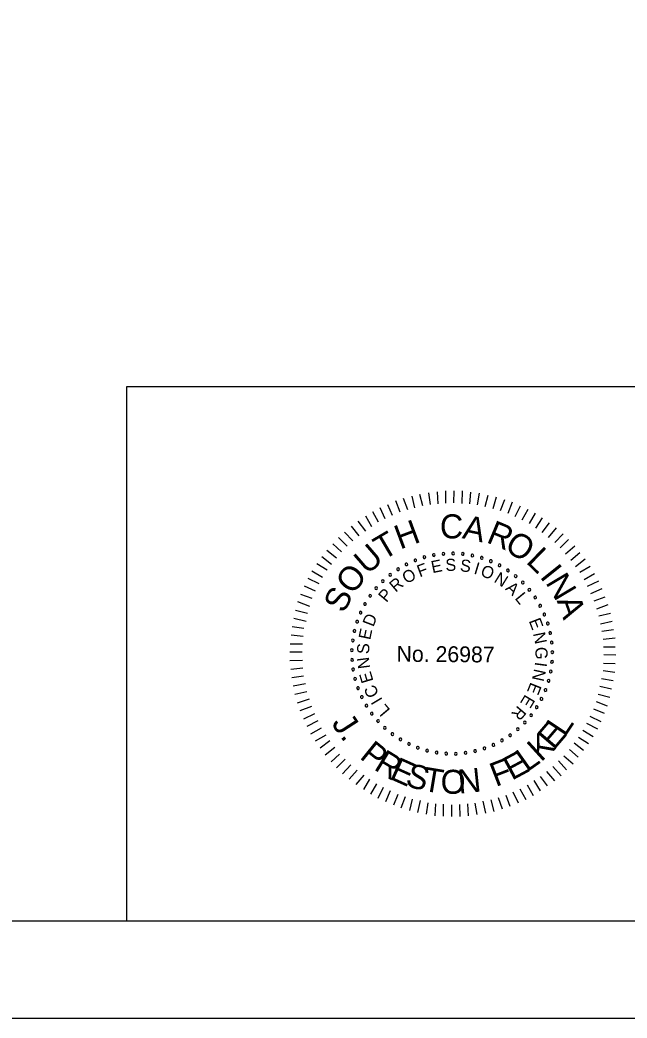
# Model space of a CAD drawing. Extents: x 96 to 240, y 601 to 689.
# Drawn here: x 184.17 to 196.67, y 601 to 621.55 of the extents above; entities that cross this region are included whole.
import ezdxf

# ---------------------------------------------------------------- set-up
doc = ezdxf.new("R2010")
doc.units = 0
for name, color, linetype in [('BR_BORDER LINES', 7, 'Continuous'), ('BR_TEXT', 7, 'Continuous'), ('Level 31', 7, 'Continuous')]:
    doc.layers.add(name, color=color, linetype=linetype)

msp = doc.modelspace()

# ---------------------------------------------------------------- linework, layer by layer
at = {"layer": 'BR_BORDER LINES'}
for p, q in [((186.375, 614.004), (207.836, 614.004)), ((186.375, 603.004), (186.375, 614.004)), ((103.173, 603.003), (237.837, 603.003))]:
    msp.add_line(p, q, dxfattribs=at)
at = {"layer": 'BR_TEXT'}
for p, q in [((192.299, 611.507), (192.246, 611.751)), ((192.464, 611.546), (192.407, 611.784)), ((192.622, 611.576), (192.586, 611.82)), ((192.78, 611.592), (192.765, 611.836)), ((192.938, 611.601), (192.94, 611.858)), ((193.106, 611.61), (193.108, 611.857)), ((193.274, 611.598), (193.283, 611.856)), ((193.435, 611.587), (193.455, 611.83)), ((193.59, 611.568), (193.633, 611.811)), ((193.751, 611.536), (193.808, 611.772)), ((193.915, 611.493), (193.979, 611.736)), ((191.841, 611.349), (191.747, 611.573)), ((191.996, 611.416), (191.912, 611.651)), ((192.154, 611.467), (192.067, 611.697)), ((194.063, 611.451), (194.15, 611.68)), ((194.22, 611.398), (194.308, 611.631)), ((194.364, 611.328), (194.475, 611.55)), ((191.413, 611.116), (191.292, 611.333)), ((191.555, 611.211), (191.433, 611.428)), ((191.693, 611.282), (191.588, 611.506)), ((194.507, 611.258), (194.633, 611.481)), ((194.658, 611.185), (194.787, 611.4)), ((191.154, 610.929), (190.995, 611.13)), ((191.289, 611.031), (191.133, 611.235)), ((194.791, 611.088), (194.927, 611.303)), ((194.924, 611.001), (195.07, 611.202)), ((191.023, 610.831), (190.856, 611.01)), ((195.054, 610.897), (195.216, 611.095)), ((195.18, 610.796), (195.353, 610.973)), ((190.788, 610.599), (190.614, 610.769)), ((190.905, 610.722), (190.728, 610.898)), ((195.292, 610.686), (195.465, 610.859)), ((195.404, 610.561), (195.595, 610.728)), ((190.687, 610.473), (190.489, 610.629)), ((195.513, 610.433), (195.7, 610.586)), ((190.496, 610.224), (190.281, 610.356)), ((190.583, 610.34), (190.385, 610.5)), ((195.608, 610.298), (195.805, 610.455)), ((195.696, 610.181), (195.907, 610.31)), ((190.399, 610.077), (190.184, 610.206)), ((195.784, 610.033), (195.998, 610.158)), ((190.259, 609.793), (190.03, 609.895)), ((190.329, 609.94), (190.103, 610.052)), ((195.855, 609.895), (196.086, 610.003)), ((190.189, 609.639), (189.957, 609.727)), ((195.926, 609.747), (196.154, 609.844)), ((190.14, 609.479), (189.894, 609.57)), ((195.994, 609.592), (196.221, 609.675)), ((196.047, 609.43), (196.278, 609.517)), ((190.091, 609.335), (189.847, 609.395)), ((196.087, 609.285), (196.328, 609.342)), ((190.062, 609.167), (189.812, 609.231)), ((196.12, 609.117), (196.361, 609.177)), ((190.001, 608.858), (189.754, 608.888)), ((190.019, 609.023), (189.776, 609.056)), ((196.153, 608.972), (196.39, 609.001)), ((189.989, 608.701), (189.732, 608.703)), ((196.179, 608.807), (196.423, 608.833)), ((189.981, 608.536), (189.73, 608.538)), ((196.185, 608.649), (196.425, 608.647)), ((196.194, 608.485), (196.438, 608.483)), ((189.986, 608.364), (189.729, 608.359)), ((196.182, 608.313), (196.422, 608.304)), ((189.996, 608.21), (189.748, 608.181)), ((190.011, 608.045), (189.767, 608.009)), ((196.174, 608.159), (196.418, 608.126)), ((190.051, 607.887), (189.8, 607.834)), ((196.11, 607.837), (196.349, 607.78)), ((196.145, 607.994), (196.382, 607.954)), ((190.077, 607.718), (189.833, 607.662)), ((196.074, 607.669), (196.314, 607.608)), ((190.124, 607.57), (189.876, 607.486)), ((196.031, 607.521), (196.261, 607.434)), ((190.171, 607.415), (189.937, 607.331)), ((190.238, 607.267), (190.007, 607.159)), ((195.905, 607.22), (196.131, 607.109)), ((195.975, 607.367), (196.201, 607.28)), ((190.306, 607.122), (190.078, 607.004)), ((195.832, 607.077), (196.061, 606.955)), ((190.373, 606.974), (190.156, 606.849)), ((190.468, 606.826), (190.251, 606.701)), ((195.759, 606.93), (195.971, 606.801)), ((190.553, 606.708), (190.353, 606.562)), ((195.578, 606.667), (195.773, 606.518)), ((195.668, 606.783), (195.877, 606.654)), ((190.655, 606.574), (190.454, 606.417)), ((190.753, 606.439), (190.577, 606.276)), ((195.37, 606.401), (195.557, 606.234)), ((195.481, 606.534), (195.665, 606.374)), ((190.869, 606.335), (190.689, 606.155)), ((190.985, 606.214), (190.815, 606.03)), ((195.256, 606.299), (195.426, 606.115)), ((191.114, 606.11), (190.952, 605.922)), ((191.248, 606.006), (191.088, 605.815)), ((195.014, 606.078), (195.173, 605.888)), ((195.142, 606.18), (195.312, 605.993)), ((191.37, 605.919), (191.245, 605.711)), ((191.51, 605.829), (191.385, 605.613)), ((194.613, 605.803), (194.739, 605.586)), ((194.748, 605.891), (194.88, 605.681)), ((194.883, 605.976), (195.025, 605.782)), ((191.647, 605.749), (191.539, 605.526)), ((191.794, 605.679), (191.696, 605.456)), ((191.948, 605.609), (191.86, 605.383)), ((194.172, 605.59), (194.256, 605.363)), ((194.317, 605.658), (194.425, 605.434)), ((194.462, 605.725), (194.583, 605.501)), ((192.105, 605.559), (192.014, 605.327)), ((192.249, 605.51), (192.192, 605.274)), ((192.414, 605.481), (192.353, 605.235)), ((192.571, 605.435), (192.532, 605.202)), ((192.729, 605.417), (192.71, 605.17)), ((192.887, 605.405), (192.885, 605.158)), ((193.055, 605.394), (193.053, 605.15)), ((193.223, 605.403), (193.228, 605.155)), ((193.384, 605.412), (193.4, 605.164)), ((193.539, 605.427), (193.578, 605.194)), ((193.701, 605.471), (193.754, 605.223)), ((193.866, 605.497), (193.926, 605.259)), ((194.014, 605.544), (194.098, 605.309))]:
    msp.add_line(p, q, dxfattribs=at)
for centre, start, end in [((192.498, 610.49), 16.1422, 196.1422), ((192.692, 610.536), 10.6038, 190.6038), ((192.692, 610.536), 190.6038, 10.6038), ((192.89, 610.563), 5.0653, 185.0653), ((192.89, 610.563), 185.0653, 5.0653), ((193.089, 610.57), 359.5268, 179.5268), ((193.089, 610.57), 179.5268, 359.5268), ((193.288, 610.558), 353.9884, 173.9884), ((193.288, 610.558), 173.9884, 353.9884), ((193.485, 610.528), 348.4499, 168.4499), ((193.485, 610.528), 168.4499, 348.4499), ((193.678, 610.478), 342.9114, 162.9114), ((192.128, 610.344), 27.2191, 207.2191), ((192.128, 610.344), 207.2191, 27.2191), ((192.31, 610.426), 21.6807, 201.6807), ((192.31, 610.426), 201.6807, 21.6807), ((192.498, 610.49), 196.1422, 16.1422), ((193.678, 610.478), 162.9114, 342.9114), ((193.865, 610.41), 157.373, 337.373), ((193.865, 610.41), 337.373, 157.373), ((194.045, 610.324), 151.8345, 331.8345), ((194.045, 610.324), 331.8345, 151.8345), ((191.793, 610.129), 38.2961, 218.2961), ((191.793, 610.129), 218.2961, 38.2961), ((191.955, 610.244), 32.7576, 212.7576), ((191.955, 610.244), 212.7576, 32.7576), ((194.216, 610.221), 146.2961, 326.2961), ((194.216, 610.221), 326.2961, 146.2961), ((194.376, 610.102), 140.7576, 320.7576), ((194.376, 610.102), 320.7576, 140.7576), ((191.642, 609.998), 43.8345, 223.8345), ((191.642, 609.998), 223.8345, 43.8345), ((194.524, 609.969), 135.2191, 315.2191), ((194.524, 609.969), 315.2191, 135.2191), ((191.382, 609.697), 54.9114, 234.9114), ((191.382, 609.697), 234.9114, 54.9114), ((191.505, 609.854), 49.373, 229.373), ((191.505, 609.854), 229.373, 49.373), ((194.658, 609.821), 129.6807, 309.6807), ((194.658, 609.821), 309.6807, 129.6807), ((194.777, 609.662), 124.1422, 304.1422), ((194.777, 609.662), 304.1422, 124.1422), ((191.275, 609.528), 60.4499, 240.4499), ((191.275, 609.528), 240.4499, 60.4499), ((194.881, 609.491), 118.6038, 298.6038), ((194.881, 609.491), 298.6038, 118.6038), ((191.185, 609.351), 65.9884, 245.9884), ((191.185, 609.351), 245.9884, 65.9884), ((194.967, 609.312), 113.0653, 293.0653), ((194.967, 609.312), 293.0653, 113.0653), ((191.113, 609.165), 71.5268, 251.5268), ((191.113, 609.165), 251.5268, 71.5268), ((195.036, 609.125), 107.5268, 287.5268), ((195.036, 609.125), 287.5268, 107.5268), ((191.058, 608.973), 77.0653, 257.0653), ((191.058, 608.973), 257.0653, 77.0653), ((195.087, 608.932), 101.9884, 281.9884), ((195.087, 608.932), 281.9884, 101.9884), ((191.023, 608.777), 82.6038, 262.6038), ((191.023, 608.777), 262.6038, 82.6038), ((195.118, 608.735), 96.4499, 276.4499), ((195.118, 608.735), 276.4499, 96.4499), ((191.006, 608.578), 88.1422, 268.1422), ((191.006, 608.578), 268.1422, 88.1422), ((195.131, 608.536), 90.9114, 270.9114), ((195.131, 608.536), 270.9114, 90.9114), ((191.009, 608.379), 93.6807, 273.6807), ((191.009, 608.379), 273.6807, 93.6807), ((195.124, 608.337), 85.373, 265.373), ((195.124, 608.337), 265.373, 85.373), ((191.031, 608.181), 99.2191, 279.2191), ((191.031, 608.181), 279.2191, 99.2191), ((195.098, 608.139), 79.8345, 259.8345), ((195.098, 608.139), 259.8345, 79.8345), ((191.072, 607.986), 104.7576, 284.7576), ((191.072, 607.986), 284.7576, 104.7576), ((195.053, 607.945), 74.2961, 254.2961), ((195.053, 607.945), 254.2961, 74.2961), ((191.132, 607.796), 110.2961, 290.2961), ((191.132, 607.796), 290.2961, 110.2961), ((191.209, 607.612), 115.8345, 295.8345), ((191.209, 607.612), 295.8345, 115.8345), ((194.989, 607.756), 68.7576, 248.7576), ((194.989, 607.756), 248.7576, 68.7576), ((191.305, 607.437), 121.373, 301.373), ((191.305, 607.437), 301.373, 121.373), ((194.809, 607.401), 57.6807, 237.6807), ((194.809, 607.401), 237.6807, 57.6807), ((194.908, 607.574), 63.2191, 243.2191), ((194.908, 607.574), 243.2191, 63.2191), ((191.416, 607.272), 126.9114, 306.9114), ((191.416, 607.272), 306.9114, 126.9114), ((194.694, 607.238), 52.1422, 232.1422), ((194.694, 607.238), 232.1422, 52.1422), ((191.543, 607.118), 132.4499, 312.4499), ((191.543, 607.118), 312.4499, 132.4499), ((194.564, 607.087), 46.6038, 226.6038), ((194.564, 607.087), 226.6038, 46.6038), ((191.684, 606.977), 137.9884, 317.9884), ((191.684, 606.977), 317.9884, 137.9884), ((191.838, 606.851), 143.5268, 323.5268), ((191.838, 606.851), 323.5268, 143.5268), ((194.263, 606.826), 35.5268, 215.5268), ((194.263, 606.826), 215.5268, 35.5268), ((194.42, 606.949), 41.0653, 221.0653), ((194.42, 606.949), 221.0653, 41.0653), ((192.004, 606.74), 149.0653, 329.0653), ((192.004, 606.74), 329.0653, 149.0653), ((192.18, 606.646), 154.6038, 334.6038), ((192.18, 606.646), 334.6038, 154.6038), ((193.918, 606.628), 24.4499, 204.4499), ((193.918, 606.628), 204.4499, 24.4499), ((194.095, 606.719), 29.9884, 209.9884), ((194.095, 606.719), 209.9884, 29.9884), ((192.363, 606.569), 160.1422, 340.1422), ((192.363, 606.569), 340.1422, 160.1422), ((192.554, 606.51), 165.6807, 345.6807), ((192.554, 606.51), 345.6807, 165.6807), ((192.749, 606.469), 351.2191, 171.2191), ((192.749, 606.469), 171.2191, 351.2191), ((192.947, 606.448), 356.7576, 176.7576), ((192.947, 606.448), 176.7576, 356.7576), ((193.146, 606.446), 2.2961, 182.2961), ((193.146, 606.446), 182.2961, 2.2961), ((193.345, 606.463), 7.8345, 187.8345), ((193.345, 606.463), 187.8345, 7.8345), ((193.541, 606.5), 13.373, 193.373), ((193.541, 606.5), 193.373, 13.373), ((193.733, 606.555), 18.9114, 198.9114), ((193.733, 606.555), 198.9114, 18.9114)]:
    msp.add_arc(centre, 0.028, start, end, dxfattribs=at)
at = {"layer": 'Level 31'}
msp.add_lwpolyline([(95.84, 689.004), (95.84, 601.004), (239.84, 601.004), (239.84, 689.004)], dxfattribs=at)

# ---------------------------------------------------------------- texts
at = {"layer": 'BR_TEXT'}
for s, height, rotation, p in [('C', 0.496, 359.5482, (192.815, 610.88)), ('A', 0.496, 348.1981, (193.261, 610.884)), ('H', 0.496, 20.3637, (191.997, 610.647)), ('R', 0.496, 337.4344, (193.754, 610.804)), ('T', 0.496, 30.4992, (191.646, 610.417)), ('O', 0.496, 326.5869, (194.123, 610.657)), ('U', 0.496, 40.8022, (191.321, 610.118)), ('L', 0.496, 315.9488, (194.573, 610.386)), ('O', 0.496, 52.0267, (191.023, 609.702)), ('F', 0.249, 20.6127, (192.402, 610.076)), ('E', 0.249, 11.4103, (192.663, 610.162)), ('S', 0.249, 2.208, (192.934, 610.206)), ('S', 0.249, 352.6608, (193.22, 610.206)), ('I', 0.249, 343.1136, (193.5, 610.157)), ('O', 0.249, 338.4392, (193.634, 610.117)), ('I', 0.496, 308.6613, (194.859, 610.089)), ('O', 0.249, 30.8477, (192.133, 609.932)), ('N', 0.249, 328.2042, (193.913, 609.991)), ('N', 0.496, 300.7037, (194.981, 609.971)), ('R', 0.249, 40.3949, (191.908, 609.756)), ('A', 0.249, 318.657, (194.149, 609.831)), ('S', 0.496, 63.2511, (190.842, 609.32)), ('P', 0.249, 49.9421, (191.716, 609.546)), ('L', 0.249, 309.4546, (194.348, 609.642)), ('A', 0.496, 289.4792, (195.218, 609.599)), ('D', 0.249, 69.0364, (191.448, 609.045)), ('E', 0.249, 291.049, (194.643, 609.181)), ('E', 0.249, 78.2388, (191.382, 608.778)), ('N', 0.249, 281.8466, (194.732, 608.921)), ('S', 0.249, 87.786, (191.359, 608.494)), ('No. 26987', 0.327, 359.5268, (191.924, 608.34)), ('G', 0.249, 272.2995, (194.779, 608.639)), ('N', 0.249, 97.3332, (191.384, 608.21)), ('I', 0.249, 262.4084, (194.778, 608.344)), ('E', 0.249, 106.5355, (191.452, 607.944)), ('N', 0.249, 257.7339, (194.759, 608.206)), ('C', 0.249, 116.4266, (191.571, 607.674)), ('E', 0.249, 248.1867, (194.687, 607.93)), ('E', 0.249, 238.9844, (194.575, 607.679)), ('I', 0.249, 121.1011, (191.644, 607.554)), ('L', 0.249, 129.9595, (191.806, 607.345)), ('R', 0.249, 229.782, (194.425, 607.449)), ('J', 0.494, 302.9559, (190.575, 607.071)), ('E', 0.494, 49.3639, (195.159, 606.504)), ('L', 0.494, 56.4247, (195.389, 606.775)), ('K', 0.494, 42.3031, (194.897, 606.263)), ('.', 0.494, 309.3974, (190.751, 606.8)), ('P', 0.494, 321.1035, (191.145, 606.363)), ('R', 0.494, 328.5359, (191.438, 606.13)), ('E', 0.494, 28.1814, (194.296, 605.887)), ('L', 0.494, 35.2422, (194.608, 606.057)), ('E', 0.494, 335.9684, (191.758, 605.938)), ('S', 0.494, 343.0292, (192.084, 605.795)), ('F', 0.494, 21.1206, (193.966, 605.758)), ('T', 0.494, 350.4617, (192.442, 605.689)), ('O', 0.494, 358.1419, (192.824, 605.629)), ('N', 0.494, 5.8221, (193.21, 605.621))]:
    msp.add_text(s, height=height, rotation=rotation, dxfattribs=at).set_placement(p)

doc.saveas('drawing.dxf')
